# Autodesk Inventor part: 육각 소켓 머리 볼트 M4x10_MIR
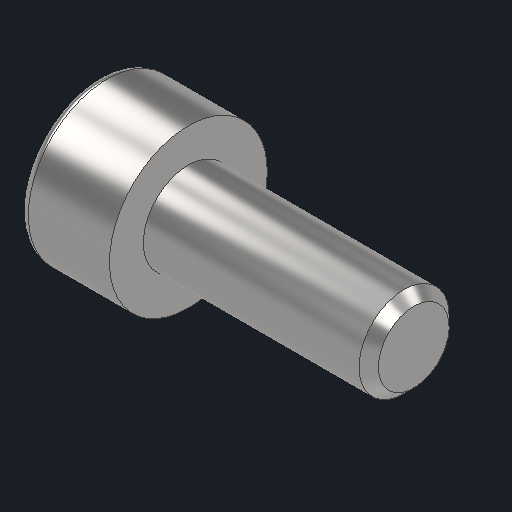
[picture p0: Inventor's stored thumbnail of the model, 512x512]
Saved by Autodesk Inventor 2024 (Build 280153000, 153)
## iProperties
Created: 2024-05
Part Number: 육각 소켓 머리 볼트 M4x10_MIR
Material: 강철, 연강
Description: 6각머리 태핑 나사
Document SubType Name: Modeling
Designer: kh_501
Density: 7.85 g/cm^3
Appearance: 기본값
Author: jhkim
Sending System: Autodesk Inventor 2025
Preprocessor: ST-DEVELOPER v20
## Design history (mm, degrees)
derived "육각 소켓 머리 볼트 M4x10.ipt"
feature "솔리드1::육각 소켓 머리 볼트 M4x10.ipt" dims "d0" = 10
tag "피쳐 태그1"
node "솔리드1"
